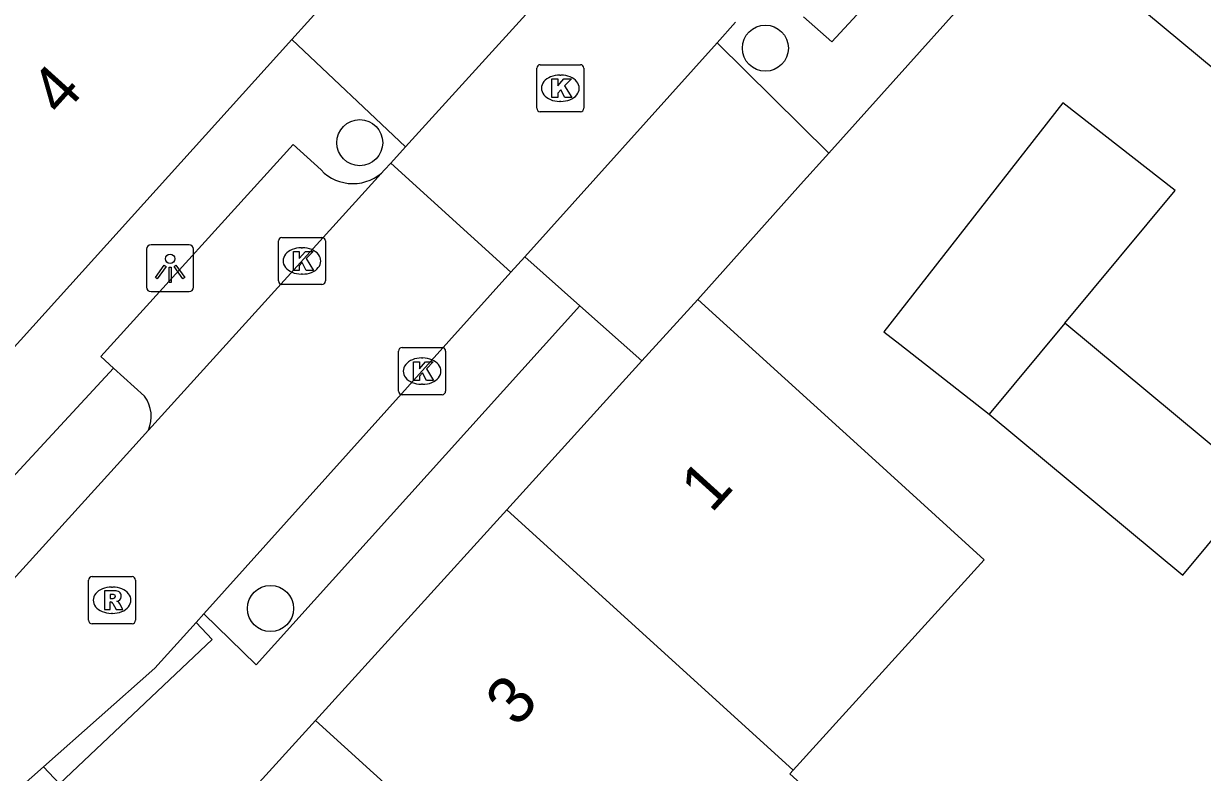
# Model space of a CAD drawing. Extents: x 161882 to 162509, y 381687 to 382379.
# Drawn here: x 162355.53 to 162380.6, y 381900.52 to 381916.43 of the extents above; entities that cross this region are included whole.
import ezdxf

# ---------------------------------------------------------------- set-up
doc = ezdxf.new("R2010")
doc.units = 0
for name, color, linetype in [('IMGEO_Boom', 7, 'Continuous'), ('IMGEO_Kolk', 7, 'Continuous'), ('IMGEO_Lichtpunt', 7, 'Continuous'), ('IMGEO_Muur', 7, 'Continuous'), ('IMGEO_Pand', 7, 'Continuous'), ('IMGEO_Pand_nummerreeks', 7, 'Continuous'), ('IMGEO_Parkeervlak_open', 7, 'Continuous'), ('IMGEO_Rijbaan_lokaal_open', 7, 'Continuous'), ('IMGEO_Rioolput', 7, 'Continuous'), ('IMGEO_Voetpad_open', 7, 'Continuous')]:
    doc.layers.add(name, color=color, linetype=linetype)

msp = doc.modelspace()

# ---------------------------------------------------------------- linework, layer by layer
at = {"layer": 'IMGEO_Boom'}
for centre in [(162371.304, 381915.913), (162362.681, 381913.904), (162360.784, 381904.006)]:
    msp.add_circle(centre, 0.489, dxfattribs=at)
at = {"layer": 'IMGEO_Kolk'}
for p, q in [((162366.445, 381914.635), (162366.445, 381915.487)), ((162366.52, 381915.561), (162367.372, 381915.561)), ((162367.446, 381915.487), (162367.446, 381914.635)), ((162366.933, 381915.341), (162366.958, 381915.341)), ((162366.956, 381914.781), (162366.931, 381914.781)), ((162367.372, 381914.561), (162366.52, 381914.561)), ((162361.026, 381911.891), (162361.878, 381911.891)), ((162360.951, 381910.965), (162360.951, 381911.817)), ((162361.439, 381911.671), (162361.464, 381911.671)), ((162361.952, 381911.817), (162361.952, 381910.965)), ((162361.462, 381911.111), (162361.437, 381911.111)), ((162361.878, 381910.891), (162361.026, 381910.891)), ((162363.506, 381908.623), (162363.506, 381909.475)), ((162363.581, 381909.549), (162364.433, 381909.549)), ((162364.507, 381909.475), (162364.507, 381908.623)), ((162363.994, 381909.329), (162364.019, 381909.329)), ((162364.017, 381908.769), (162363.992, 381908.769)), ((162364.433, 381908.549), (162363.581, 381908.549))]:
    msp.add_line(p, q, dxfattribs=at)
for points in [[(162366.445, 381914.635), (162366.445, 381915.487)], [(162366.52, 381915.561), (162367.372, 381915.561)], [(162367.446, 381915.487), (162367.446, 381914.635)], [(162366.766, 381915.261), (162366.889, 381915.261), (162366.889, 381915.11), (162367.019, 381915.261), (162367.183, 381915.261), (162367.037, 381915.11), (162367.19, 381914.861), (162367.038, 381914.861), (162366.953, 381915.025), (162366.889, 381914.958), (162366.889, 381914.861), (162366.766, 381914.861), (162366.766, 381915.261)], [(162367.372, 381914.561), (162366.52, 381914.561)], [(162361.026, 381911.891), (162361.878, 381911.891)], [(162360.951, 381910.965), (162360.951, 381911.817)], [(162361.952, 381911.817), (162361.952, 381910.965)], [(162361.272, 381911.591), (162361.395, 381911.591), (162361.395, 381911.44), (162361.525, 381911.591), (162361.689, 381911.591), (162361.543, 381911.44), (162361.696, 381911.191), (162361.544, 381911.191), (162361.459, 381911.355), (162361.395, 381911.288), (162361.395, 381911.191), (162361.272, 381911.191), (162361.272, 381911.591)], [(162361.878, 381910.891), (162361.026, 381910.891)], [(162363.506, 381908.623), (162363.506, 381909.475)], [(162363.581, 381909.549), (162364.433, 381909.549)], [(162364.507, 381909.475), (162364.507, 381908.623)], [(162363.827, 381909.249), (162363.95, 381909.249), (162363.95, 381909.098), (162364.08, 381909.249), (162364.244, 381909.249), (162364.098, 381909.098), (162364.251, 381908.849), (162364.099, 381908.849), (162364.014, 381909.013), (162363.95, 381908.946), (162363.95, 381908.849), (162363.827, 381908.849), (162363.827, 381909.249)], [(162364.433, 381908.549), (162363.581, 381908.549)]]:
    msp.add_lwpolyline(points, dxfattribs=at)
for centre, start, end in [((162366.522, 381915.485), 91.552, 178.448), ((162366.522, 381915.485), 91.552, 178.448), ((162367.37, 381915.485), 1.552, 88.448), ((162367.37, 381915.485), 1.552, 88.448), ((162366.522, 381914.637), 181.552, 268.448), ((162366.522, 381914.637), 181.552, 268.448), ((162367.37, 381914.637), 271.552, 358.448), ((162367.37, 381914.637), 271.552, 358.448), ((162361.028, 381911.815), 91.552, 178.448), ((162361.028, 381911.815), 91.552, 178.448), ((162361.876, 381911.815), 1.552, 88.448), ((162361.876, 381911.815), 1.552, 88.448), ((162361.028, 381910.967), 181.552, 268.448), ((162361.028, 381910.967), 181.552, 268.448), ((162361.876, 381910.967), 271.552, 358.448), ((162361.876, 381910.967), 271.552, 358.448), ((162363.583, 381909.473), 91.552, 178.448), ((162363.583, 381909.473), 91.552, 178.448), ((162364.431, 381909.473), 1.552, 88.448), ((162364.431, 381909.473), 1.552, 88.448), ((162363.583, 381908.625), 181.552, 268.448), ((162363.583, 381908.625), 181.552, 268.448), ((162364.431, 381908.625), 271.552, 358.448), ((162364.431, 381908.625), 271.552, 358.448)]:
    msp.add_arc(centre, 0.0765, start, end, dxfattribs=at)
for centre, major_axis, ratio, start_param, end_param in [((162366.932, 381915.061), (-0.387, 0.002), 0.722429, 4.712389, 7.853982), ((162366.957, 381915.061), (-0.39, 0.002), 0.717154, 1.570796, 4.712389), ((162361.438, 381911.391), (-0.387, 0.002), 0.722429, 4.712389, 7.853982), ((162361.463, 381911.391), (-0.39, 0.002), 0.717154, 1.570796, 4.712389), ((162363.993, 381909.049), (-0.387, 0.002), 0.722429, 4.712389, 7.853982), ((162364.018, 381909.049), (-0.39, 0.002), 0.717154, 1.570796, 4.712389)]:
    msp.add_ellipse(centre, major_axis=major_axis, ratio=ratio, start_param=start_param, end_param=end_param, dxfattribs=at)
at = {"layer": 'IMGEO_Lichtpunt'}
for p, q in [((162358.15, 381911.64), (162358.15, 381910.833)), ((162358.15, 381911.64), (162358.15, 381910.833)), ((162359.052, 381911.735), (162358.244, 381911.735)), ((162359.052, 381911.735), (162358.244, 381911.735)), ((162359.146, 381910.833), (162359.146, 381911.64)), ((162359.146, 381910.833), (162359.146, 381911.64)), ((162358.244, 381910.739), (162359.052, 381910.739)), ((162358.244, 381910.739), (162359.052, 381910.739))]:
    msp.add_line(p, q, dxfattribs=at)
for points in [[(162358.524, 381911.304), (162358.563, 381911.276), (162358.375, 381911.014), (162358.337, 381911.041), (162358.524, 381911.304)], [(162358.626, 381911.256), (162358.673, 381911.256), (162358.673, 381910.934), (162358.626, 381910.934), (162358.626, 381911.256)], [(162358.736, 381911.276), (162358.774, 381911.303), (162358.961, 381911.041), (162358.922, 381911.013), (162358.736, 381911.276)]]:
    msp.add_lwpolyline(points, dxfattribs=at)
msp.add_circle((162358.649, 381911.438), 0.0994, dxfattribs=at)
for centre, start, end in [((162358.244, 381911.64), 90, 180), ((162358.244, 381911.64), 90, 180), ((162359.052, 381911.64), 0, 90), ((162359.052, 381911.64), 0, 90), ((162358.244, 381910.833), 180, 270), ((162358.244, 381910.833), 180, 270), ((162359.052, 381910.833), 270, 0), ((162359.052, 381910.833), 270, 360)]:
    msp.add_arc(centre, 0.0946, start, end, dxfattribs=at)
at = {"layer": 'IMGEO_Muur'}
for points in [[(162377.065, 381918.605), (162372.654, 381913.683)], [(162372.654, 381913.683), (162372.054, 381913.013)]]:
    msp.add_lwpolyline(points, dxfattribs=at)
at = {"layer": 'IMGEO_Pand'}
for points in [[(162381.619, 381914.822), (162380.911, 381915.41), (162377.065, 381918.605)], [(162361.239, 381916.098), (162362.239, 381917.205)], [(162361.239, 381916.098), (162354.94, 381909.125)], [(162377.671, 381910.07), (162380.015, 381912.891), (162377.626, 381914.754), (162373.826, 381909.882), (162374.161, 381909.62), (162376.064, 381908.136)], [(162368.679, 381909.266), (162369.869, 381910.575)], [(162369.869, 381910.575), (162373.57, 381907.213), (162375.958, 381905.043), (162371.892, 381900.569)], [(162377.671, 381910.07), (162376.064, 381908.136)], [(162376.064, 381908.136), (162380.179, 381904.716), (162381.786, 381906.65), (162377.671, 381910.07)], [(162365.805, 381906.102), (162368.679, 381909.266)], [(162361.741, 381901.629), (162365.805, 381906.102)], [(162371.892, 381900.569), (162365.805, 381906.102)], [(162371.892, 381900.569), (162371.822, 381900.491), (162373.921, 381898.584), (162369.929, 381894.191), (162365.442, 381898.267), (162361.741, 381901.629)]]:
    msp.add_lwpolyline(points, dxfattribs=at)
at = {"layer": 'IMGEO_Parkeervlak_open'}
msp.add_lwpolyline([(162358.106, 381908.515), (162357.444, 381909.116)], dxfattribs=at)
msp.add_arc((162357.522, 381908.083), 0.727, 336.6074, 36.5263, dxfattribs=at)
at = {"layer": 'IMGEO_Rijbaan_lokaal_open'}
for points in [[(162367.769, 381918.348), (162363.656, 381913.817)], [(162370.672, 381916.467), (162370.278, 381916.028)], [(162370.278, 381916.028), (162366.189, 381911.476)], [(162363.341, 381913.47), (162363.656, 381913.817)], [(162363.341, 381913.47), (162363.209, 381913.324)], [(162365.896, 381911.151), (162363.341, 381913.47)], [(162363.209, 381913.324), (162358.189, 381907.794)], [(162366.189, 381911.476), (162365.896, 381911.151)], [(162359.367, 381903.893), (162365.896, 381911.151)], [(162358.189, 381907.794), (162357.389, 381906.913), (162354.336, 381903.551)], [(162359.367, 381903.893), (162359.203, 381903.711)], [(162355.955, 381900.643), (162358.327, 381902.737), (162359.203, 381903.711)], [(162355.955, 381900.643), (162354.961, 381899.766)]]:
    msp.add_lwpolyline(points, dxfattribs=at)
at = {"layer": 'IMGEO_Rioolput'}
for p, q in [((162356.915, 381903.756), (162356.915, 381904.608)), ((162356.99, 381904.682), (162357.842, 381904.682)), ((162357.916, 381904.608), (162357.916, 381903.756)), ((162357.403, 381904.462), (162357.428, 381904.462)), ((162357.426, 381903.902), (162357.401, 381903.902)), ((162357.842, 381903.682), (162356.99, 381903.682))]:
    msp.add_line(p, q, dxfattribs=at)
for points in [[(162356.915, 381903.756), (162356.915, 381904.608)], [(162356.99, 381904.682), (162357.842, 381904.682)], [(162357.916, 381904.608), (162357.916, 381903.756)], [(162357.504, 381904.38), (162357.252, 381904.382), (162357.252, 381903.982)], [(162357.252, 381903.982), (162357.376, 381903.982), (162357.376, 381904.144), (162357.387, 381904.144)], [(162357.43, 381904.301), (162357.376, 381904.301), (162357.376, 381904.22)], [(162357.376, 381904.22), (162357.428, 381904.22)], [(162357.434, 381904.115), (162357.505, 381903.982), (162357.645, 381903.982), (162357.58, 381904.108)], [(162357.842, 381903.682), (162356.99, 381903.682)]]:
    msp.add_lwpolyline(points, dxfattribs=at)
for centre, radius, start, end in [((162356.992, 381904.606), 0.0765, 91.552, 178.448), ((162356.992, 381904.606), 0.0765, 91.552, 178.448), ((162357.84, 381904.606), 0.0765, 1.552, 88.448), ((162357.84, 381904.606), 0.0765, 1.552, 88.448), ((162357.503, 381904.27), 0.109, 350.3612, 89.416), ((162357.386, 381904.091), 0.0533, 26.0293, 88.6989), ((162357.412, 381904.409), 0.19, 274.7715, 282.9687), ((162357.436, 381904.205), 0.0964, 77.0061, 93.1865), ((162357.45, 381904.262), 0.0378, 276.6634, 79.6772), ((162357.501, 381904.27), 0.112, 277.5842, 350.9817), ((162357.485, 381904.055), 0.108, 29.5134, 73.7905), ((162356.992, 381903.758), 0.0765, 181.552, 268.448), ((162356.992, 381903.758), 0.0765, 181.552, 268.448), ((162357.84, 381903.758), 0.0765, 271.552, 358.448), ((162357.84, 381903.758), 0.0765, 271.552, 358.448)]:
    msp.add_arc(centre, radius, start, end, dxfattribs=at)
for centre, major_axis, ratio, start_param, end_param in [((162357.402, 381904.182), (-0.387, 0.002), 0.722429, 4.712389, 7.853982), ((162357.427, 381904.182), (-0.39, 0.002), 0.717154, 1.570796, 4.712389)]:
    msp.add_ellipse(centre, major_axis=major_axis, ratio=ratio, start_param=start_param, end_param=end_param, dxfattribs=at)
at = {"layer": 'IMGEO_Voetpad_open'}
for points in [[(162372.118, 381916.58), (162372.714, 381916.046), (162379.399, 381923.266), (162380.121, 381924.063), (162379.503, 381924.613)], [(162377.065, 381918.605), (162372.654, 381913.683)], [(162363.656, 381913.817), (162361.239, 381916.098)], [(162372.654, 381913.683), (162370.278, 381916.028)], [(162357.444, 381909.116), (162357.177, 381909.358), (162361.266, 381913.862), (162361.858, 381913.325)], [(162372.654, 381913.683), (162372.054, 381913.013), (162369.869, 381910.575)], [(162367.357, 381910.439), (162366.189, 381911.476)], [(162367.357, 381910.439), (162360.479, 381902.81), (162359.367, 381903.893)], [(162368.679, 381909.266), (162367.357, 381910.439)], [(162357.444, 381909.116), (162353.626, 381904.992), (162352.601, 381905.888), (162351.3, 381904.448), (162351.235, 381904.201)], [(162359.203, 381903.711), (162359.546, 381903.348), (162356.298, 381900.28), (162355.955, 381900.643)], [(162341.358, 381879.213), (162361.741, 381901.629)]]:
    msp.add_lwpolyline(points, dxfattribs=at)
msp.add_arc((162362.534, 381913.968), 0.933, 223.5604, 316.3548, dxfattribs=at)

# ---------------------------------------------------------------- texts
at = {"layer": 'IMGEO_Pand_nummerreeks'}
for s, rotation, p in [('4', 47.905, (162356.336, 381914.428)), ('1', 47.7429, (162370.156, 381906.013)), ('3', 47.7429, (162366.015, 381901.456))]:
    msp.add_text(s, height=1, rotation=rotation, dxfattribs=at).set_placement(p)

doc.saveas('drawing.dxf')
